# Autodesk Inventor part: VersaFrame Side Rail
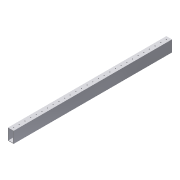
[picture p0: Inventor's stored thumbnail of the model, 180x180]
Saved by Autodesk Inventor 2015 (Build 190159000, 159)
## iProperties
Created: 2014-12
Part Number: VersaFrame Side Rail
Material: Aluminum 6061
Document SubType Name: Modeling
Designer: Nemo
Density: 2.7 g/cm^3
Appearance: Aluminum - Flat
Length: 28.000 in
HoleOffset: 0.500 in
Author: Nemo
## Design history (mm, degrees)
sketch "Sketch1"
  geometry: L1 (12.7, -25.4)-(-12.7, -25.4); L2 (-12.7, -25.4)-(-12.7, 25.4); L3 (-12.7, 25.4)-(12.7, 25.4); L4 (12.7, 25.4)-(12.7, -25.4); L5 (12.7, -25.4)-(-12.7, 25.4); L6 (-12.7, -25.4)-(12.7, 25.4); L7 (10.16, 22.86)-(-10.16, 22.86); L8 (-10.16, 22.86)-(-10.16, -22.86); L9 (-10.16, -22.86)-(10.16, -22.86); L10 (10.16, -22.86)-(10.16, 22.86); 1 further point
  constraints: 20 end point, 4 parallel, 2 midpoint, 2 perpendicular, 1 horizontal, 3 other
  dimensions: "d0" = 25.4 distance of L2.end L3.end; "d1" = 50.8 distance of L1.end L2.end; "d2" = 2.54 distance between parallel lines of L3 L7
extrude "Extrusion1" new body sketch "Sketch1" taper "d4" = 0 deg; stored distance "Length" = 711.2
sketch "Sketch2"
  geometry: 3 further points
  constraints: 2 vertical alignment
  dimensions: "HoleOffset" = 12.7 distance of point (12.7, 355.6) point (12.7, 368.3); "d6" = 12.7 distance of point (12.7, 355.6) point (12.7, 342.9) (computed from HoleOffset)
hole "Hole1" sketch "Sketch2" at (12.7, 368.3), (12.7, 342.9) diameter "d7" = 4.1656; stored, may be unused: countersink angle "d11" = 82 deg, drill point angle "d13" = 118 deg; dims "d8" = 19.05, "d9" = 9.525, "d10" = 6.35, "d12" = 25.4
body "Solid1"
pattern_linear "Rectangular Pattern1" dims "d16" = 50.8
